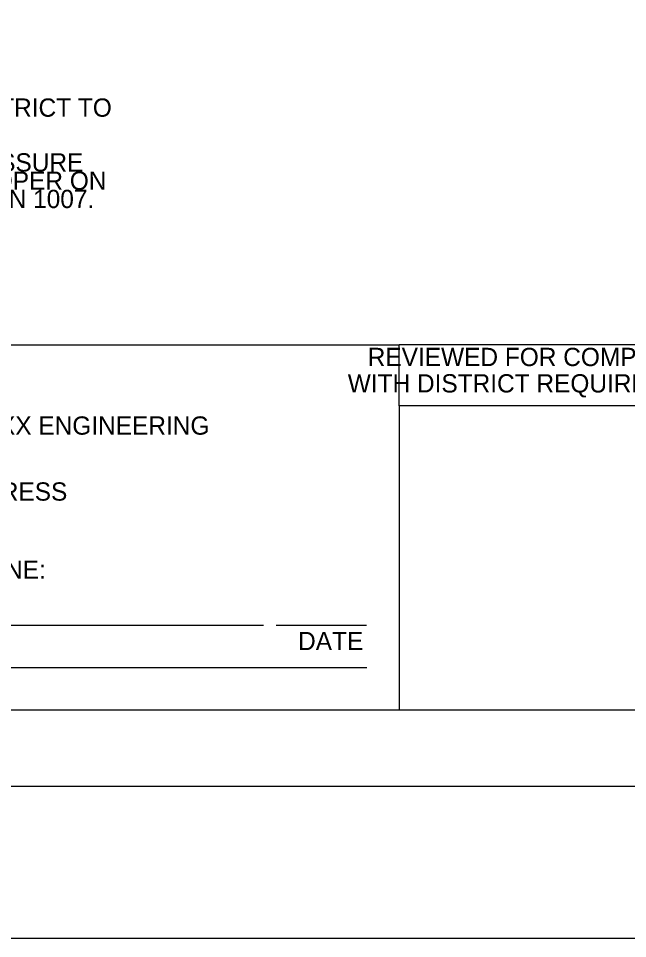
# Model space of a CAD drawing. Extents: x 837 to 1117, y 1316 to 1424.
# Drawn here: x 862.75 to 866.75, y 1398.24 to 1404.28 of the extents above; entities that cross this region are included whole.
import ezdxf

# ---------------------------------------------------------------- set-up
doc = ezdxf.new("R2010")
doc.units = 0
for name, color, linetype in [('0 (Construction)', 7, 'Continuous'), ('BASEMAP', 7, 'Continuous'), ('LLINES', 7, 'Continuous'), ('TEXT', 7, 'Continuous')]:
    doc.layers.add(name, color=color, linetype=linetype)

msp = doc.modelspace()

# ---------------------------------------------------------------- linework, layer by layer
at = {"layer": '0 (Construction)'}
msp.add_lwpolyline([(841.77, 1422.24), (877.77, 1422.24), (877.77, 1398.24), (841.77, 1398.24)], close=True, dxfattribs=at)
at = {"layer": 'BASEMAP'}
for p, q in [((864.3642, 1400.2972), (862.2183, 1400.2972)), ((864.3642, 1400.2972), (862.2183, 1400.2972)), ((865.04, 1400.2967), (864.4456, 1400.2967)), ((862.2195, 1400.0198), (865.0412, 1400.0198)), ((862.2195, 1400.0198), (865.0412, 1400.0198)), ((876.52, 1399.74), (843.52, 1399.74)), ((877.02, 1399.24), (843.02, 1399.24))]:
    msp.add_line(p, q, dxfattribs=at)
for points in [[(862.0052, 1402.14), (865.2552, 1402.14)], [(867.2552, 1402.14), (865.2552, 1402.14)], [(865.2552, 1401.74), (865.2552, 1402.14)], [(867.2552, 1401.74), (865.2552, 1401.74)], [(865.2552, 1401.74), (865.2552, 1399.74)]]:
    msp.add_lwpolyline(points, dxfattribs=at)

# ---------------------------------------------------------------- texts
for s, p in [('REVIEWED FOR COMPLIANCE', (865.048, 1402.0002)), ('WITH DISTRICT REQUIREMENTS', (864.9168, 1401.8269)), ('ADDRESS', (862.2994, 1401.1164)), ('PHONE: ', (862.3187, 1400.6033))]:
    msp.add_text(s, height=0.12, dxfattribs=at).set_placement(p)
at = {"layer": 'LLINES'}
msp.add_text('DATE ', height=0.12, dxfattribs=at).set_placement((864.5906, 1400.1345))
at = {"layer": 'TEXT'}
for s, p in [('1. APPROVAL OF THESE PLANS DO NOT CONSTRUE, IN ANY WAY, A COMMITMENT BY THE DISTRICT TO', (855.2361, 1403.638)), ('2. FOR ALL DOMESTIC WATER METERS WITH STATIC PRESSURE OF 80 PSI OR GREATER, PRESSURE ', (855.2361, 1403.278)), ('    REGULATORS ARE REQUIRED TO BE INSTALLED AND MAINTAINED BY THE OWNER / DEVELOPER ON', (855.2361, 1403.158)), ('    HIS/HER SIDE OF THE WATER METER PER LOS ANGELES COUNTY PLUMBING CODE, SECTION 1007.', (855.2361, 1403.038)), ('XXXXX ENGINEERING', (862.3052, 1401.5497))]:
    msp.add_text(s, height=0.12, dxfattribs=at).set_placement(p)

doc.saveas('drawing.dxf')
